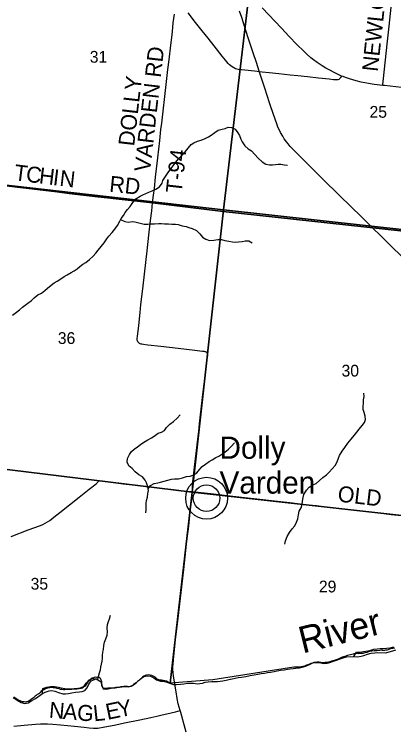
# Model space of a CAD drawing. Extents: x 1410790 to 1770854, y 566777 to 831614.
# Drawn here: x 1630046 to 1637179, y 668904 to 682381 of the extents above; entities that cross this region are included whole.
import ezdxf

# ---------------------------------------------------------------- set-up
doc = ezdxf.new("R2010")
doc.units = 0
for name, color, linetype in [('GM_X_County_Road', 7, 'Continuous'), ('GM_X_County_Road_Text', 7, 'Continuous'), ('GM_X_Major_River', 7, 'Continuous'), ('GM_X_Major_River_Text', 7, 'Continuous'), ('GM_X_Minor_River', 7, 'Continuous'), ('GM_X_Rail_Line', 7, 'Continuous'), ('GM_X_Section', 7, 'Continuous'), ('GM_X_Section_Text', 7, 'Continuous'), ('GM_X_State_Route', 7, 'Continuous'), ('GM_X_Township', 7, 'Continuous'), ('GM_X_Township_Road', 7, 'Continuous'), ('GM_X_Township_Road_Text', 7, 'Continuous'), ('GM_X_Unincorporated', 7, 'Continuous'), ('GM_X_Unincorporated_Location', 7, 'Continuous'), ('GM_X_Unincorporated_Text', 7, 'Continuous')]:
    doc.layers.add(name, color=color, linetype=linetype)

msp = doc.modelspace()

# ---------------------------------------------------------------- linework, layer by layer
at = {"layer": 'GM_X_County_Road'}
for points in [[(1636200, 681222), (1636180, 681193), (1636170, 681181), (1636159, 681170), (1636145, 681159), (1636129, 681152), (1636112, 681149), (1636095, 681148), (1636046, 681151), (1635964, 681160), (1635768, 681184), (1635556, 681207), (1635377, 681226), (1635230, 681240), (1635018, 681262), (1634838, 681281), (1634708, 681296), (1634561, 681311), (1634382, 681329), (1634317, 681336), (1634284, 681341), (1634254, 681346), (1634229, 681353), (1634208, 681360), (1634188, 681369), (1634173, 681376), (1634144, 681393), (1634117, 681413), (1634092, 681434), (1634068, 681458), (1634014, 681520), (1633953, 681597), (1633802, 681791), (1633689, 681932), (1633577, 682073), (1633455, 682228), (1633313, 682408)], [(1628105, 674058), (1628109, 674057), (1628154, 674047), (1628219, 674034), (1628284, 674024), (1628365, 674014), (1628512, 673998), (1628789, 673966), (1629017, 673938), (1629164, 673921), (1629408, 673892), (1629685, 673861), (1629782, 673849), (1630157, 673802), (1630320, 673782), (1630483, 673762), (1631020, 673696), (1631167, 673679), (1631509, 673637), (1631640, 673621)], [(1631640, 673621), (1631720, 673611), (1631916, 673586), (1632095, 673563), (1632323, 673536), (1632681, 673494), (1632991, 673457), (1633333, 673419), (1633393, 673413)], [(1633393, 673413), (1633790, 673372), (1634051, 673342), (1634377, 673303), (1634605, 673278), (1634996, 673233), (1635224, 673207), (1635420, 673186), (1635583, 673168), (1635730, 673150), (1635860, 673135), (1636072, 673111), (1636398, 673073), (1636675, 673040), (1636854, 673019), (1637131, 672987), (1637392, 672959)]]:
    msp.add_lwpolyline(points, dxfattribs=at)
at = {"layer": 'GM_X_Major_River'}
for points in [[(1636430, 670314), (1636482, 670397), (1636542, 670398), (1636614, 670407), (1636691, 670421), (1636748, 670436), (1636806, 670451), (1636875, 670463), (1636925, 670466), (1636975, 670467), (1637044, 670472), (1637116, 670481), (1637183, 670495)], [(1636430, 670314), (1636498, 670307), (1636569, 670323), (1636621, 670334), (1636690, 670359), (1636755, 670378), (1636827, 670388), (1636877, 670389), (1637030, 670386), (1637095, 670403), (1637165, 670423), (1637220, 670444)], [(1631583, 669895), (1631681, 669841), (1631683, 669774), (1631714, 669708), (1631786, 669704), (1631837, 669715), (1631897, 669730), (1631952, 669737), (1632026, 669743), (1632117, 669750), (1632191, 669744), (1632266, 669771), (1632344, 669829), (1632411, 669890), (1632482, 669941), (1632553, 669953), (1632607, 669944), (1632667, 669913), (1632718, 669876), (1632792, 669854), (1632852, 669853), (1632912, 669836), (1632982, 669806), (1633040, 669791), (1633098, 669788), (1633171, 669794), (1633231, 669803), (1633303, 669812), (1633362, 669817), (1633416, 669813), (1633482, 669800), (1633534, 669807), (1633585, 669818), (1633635, 669831), (1633694, 669842), (1633758, 669849), (1633815, 669848), (1633865, 669849), (1633915, 669854), (1633969, 669860), (1634028, 669871), (1634080, 669882), (1634143, 669897), (1634199, 669908), (1634254, 669919), (1634320, 669930), (1634399, 669942), (1634478, 669956), (1634556, 669969), (1634625, 669982), (1634685, 669994), (1634752, 670005), (1634806, 670014), (1634865, 670023), (1634931, 670035), (1634988, 670046), (1635050, 670057), (1635121, 670066), (1635185, 670076), (1635236, 670083), (1635288, 670092), (1635340, 670099), (1635411, 670106), (1635486, 670123), (1635540, 670139), (1635609, 670174), (1635672, 670201), (1635740, 670206), (1635807, 670198), (1635859, 670187), (1635927, 670190), (1635979, 670201), (1636030, 670224), (1636101, 670248), (1636174, 670275), (1636228, 670290), (1636295, 670307), (1636430, 670314)], [(1630573, 669620), (1630583, 669714), (1630656, 669739), (1630725, 669754), (1630801, 669750), (1630875, 669737), (1630927, 669725), (1630999, 669712), (1631065, 669709), (1631116, 669710), (1631172, 669712), (1631242, 669719), (1631293, 669726), (1631360, 669759), (1631399, 669818), (1631455, 669879), (1631521, 669902), (1631583, 669895)], [(1630573, 669620), (1630626, 669643), (1630699, 669670), (1630749, 669675), (1630807, 669666), (1630875, 669638), (1630957, 669617), (1631011, 669615), (1631068, 669624), (1631128, 669633), (1631197, 669644), (1631269, 669650), (1631319, 669659), (1631370, 669676), (1631417, 669730), (1631447, 669795), (1631494, 669856), (1631583, 669895)], [(1630025, 669547), (1630101, 669496), (1630174, 669452), (1630242, 669435), (1630307, 669445), (1630378, 669488), (1630443, 669529), (1630573, 669620)]]:
    msp.add_lwpolyline(points, dxfattribs=at)
at = {"layer": 'GM_X_Minor_River'}
for points in [[(1632636, 679065), (1632709, 679098), (1632779, 679137), (1632824, 679207), (1632841, 679259), (1632888, 679331), (1632942, 679408), (1632989, 679478), (1633036, 679535), (1633081, 679605), (1633133, 679669), (1633202, 679734), (1633259, 679795), (1633314, 679869), (1633369, 679935), (1633419, 679966), (1633493, 679997), (1633560, 680017), (1633634, 680048), (1633697, 680079), (1633749, 680113), (1633814, 680158), (1633882, 680202), (1633953, 680223), (1634011, 680238), (1634069, 680258), (1634132, 680255), (1634197, 680221), (1634251, 680154), (1634282, 680103), (1634308, 680037), (1634331, 679985), (1634383, 679912), (1634442, 679854), (1634506, 679815), (1634566, 679748), (1634631, 679681), (1634707, 679612), (1634778, 679566), (1634846, 679553), (1634901, 679552), (1634955, 679558), (1635009, 679567), (1635059, 679567), (1635123, 679556), (1635185, 679549)], [(1630009, 676728), (1630088, 676783), (1630142, 676831), (1630197, 676880), (1630252, 676916), (1630302, 676957), (1630367, 677007), (1630419, 677056), (1630488, 677108), (1630557, 677145), (1630619, 677192), (1630670, 677234), (1630736, 677291), (1630793, 677335), (1630851, 677370), (1630920, 677412), (1630983, 677453), (1631041, 677485), (1631114, 677530), (1631172, 677563), (1631227, 677601), (1631277, 677642), (1631334, 677684), (1631390, 677721), (1631461, 677775), (1631530, 677838), (1631578, 677896), (1631621, 677949), (1631680, 678021), (1631735, 678086), (1631785, 678160), (1631824, 678216), (1631883, 678285), (1631934, 678347), (1631984, 678416), (1632029, 678492), (1632054, 678544), (1632098, 678604), (1632131, 678655), (1632176, 678711), (1632224, 678770), (1632273, 678844), (1632332, 678912), (1632413, 678965), (1632465, 678990), (1632522, 679012), (1632574, 679037), (1632636, 679065)], [(1632045, 678525), (1632123, 678491), (1632194, 678478), (1632264, 678486), (1632314, 678483), (1632388, 678462), (1632440, 678448), (1632490, 678439), (1632558, 678437), (1632614, 678444), (1632684, 678443), (1632761, 678451), (1632815, 678454), (1632871, 678447), (1632943, 678443), (1633007, 678440), (1633077, 678437), (1633129, 678431), (1633203, 678410), (1633275, 678395), (1633329, 678377), (1633391, 678356), (1633469, 678321), (1633533, 678257), (1633584, 678196), (1633650, 678155), (1633716, 678134), (1633798, 678136), (1633870, 678149), (1633941, 678152), (1634005, 678134), (1634077, 678117), (1634149, 678106), (1634205, 678103), (1634259, 678107), (1634331, 678116), (1634387, 678126), (1634453, 678123), (1634519, 678090)], [(1635133, 672426), (1635148, 672492), (1635179, 672569), (1635218, 672643), (1635273, 672717), (1635323, 672768), (1635354, 672838), (1635375, 672904), (1635387, 672978), (1635400, 673048), (1635437, 673112), (1635458, 673181), (1635466, 673235), (1635475, 673304), (1635489, 673357), (1635538, 673439), (1635591, 673495), (1635662, 673542), (1635720, 673569), (1635787, 673621), (1635847, 673678), (1635914, 673732), (1635969, 673777), (1636025, 673839), (1636082, 673904), (1636115, 673974), (1636144, 674042), (1636162, 674094), (1636211, 674173), (1636260, 674243), (1636315, 674325), (1636380, 674398), (1636435, 674470), (1636489, 674533), (1636532, 674587), (1636589, 674656), (1636633, 674714), (1636650, 674766), (1636645, 674830), (1636627, 674900), (1636608, 674958), (1636608, 675009), (1636611, 675079), (1636609, 675137), (1636622, 675201), (1636617, 675265)], [(1632519, 673013), (1632527, 673073), (1632528, 673139), (1632525, 673195), (1632533, 673249), (1632548, 673307), (1632559, 673381), (1632571, 673435), (1632556, 673501), (1632532, 673576), (1632509, 673630), (1632457, 673691), (1632388, 673731), (1632320, 673784), (1632260, 673847), (1632201, 673900), (1632169, 673970), (1632176, 674038), (1632211, 674114), (1632249, 674165), (1632300, 674213), (1632365, 674256), (1632417, 674296), (1632484, 674341), (1632556, 674387), (1632623, 674424), (1632673, 674454), (1632750, 674509), (1632816, 674530), (1632869, 674564), (1632909, 674617), (1632970, 674683), (1633041, 674734), (1633106, 674794), (1633166, 674857)], [(1632564, 673465), (1632608, 673527), (1632673, 673568), (1632743, 673580), (1632793, 673593), (1632864, 673612), (1632932, 673628), (1633004, 673649), (1633058, 673653), (1633135, 673654), (1633207, 673673), (1633283, 673696), (1633354, 673706), (1633404, 673723), (1633476, 673766), (1633535, 673834), (1633576, 673888), (1633638, 673931), (1633711, 673980), (1633766, 674014), (1633834, 674057), (1633889, 674079), (1633951, 674118), (1634004, 674152), (1634074, 674209), (1634123, 674261), (1634184, 674332)], [(1631612, 669879), (1631631, 669939), (1631645, 670007), (1631664, 670065), (1631674, 670117), (1631687, 670171), (1631700, 670229), (1631706, 670281), (1631703, 670337), (1631709, 670397), (1631720, 670449), (1631730, 670521), (1631743, 670583), (1631764, 670651), (1631789, 670717), (1631797, 670777), (1631794, 670849), (1631801, 670919), (1631819, 670971), (1631836, 671023), (1631854, 671093)]]:
    msp.add_lwpolyline(points, dxfattribs=at)
at = {"layer": 'GM_X_Rail_Line'}
msp.add_lwpolyline([(1637329, 677836), (1637141, 678021), (1636581, 678568), (1636163, 678979), (1635850, 679285), (1635368, 679758), (1635318, 679811), (1635235, 679897), (1635194, 679948), (1635166, 679984), (1635123, 680044), (1635092, 680093), (1635052, 680163), (1635024, 680220), (1635004, 680264), (1634988, 680304), (1634948, 680409), (1634869, 680645), (1634846, 680717), (1634800, 680857), (1634754, 680995), (1634707, 681142), (1634650, 681314), (1634598, 681475), (1634537, 681659), (1634445, 681942), (1634367, 682178), (1634321, 682319), (1634280, 682441)], dxfattribs=at)
at = {"layer": 'GM_X_Section'}
for points in [[(1629292, 684562), (1634606, 684004), (1633977, 678706), (1628678, 679311)], [(1634606, 684004), (1639895, 683441), (1639320, 678118), (1633977, 678706)], [(1628678, 679311), (1633977, 678706), (1633389, 673402), (1628111, 674047), (1628145, 674379)], [(1633977, 678706), (1639320, 678118), (1638802, 672801), (1633389, 673402)]]:
    msp.add_lwpolyline(points, close=True, dxfattribs=at)
for points in [[(1628111, 674047), (1633389, 673402), (1632979, 669812), (1632965, 669812), (1632937, 669831), (1632907, 669851), (1632879, 669862), (1632843, 669868), (1632815, 669874), (1632791, 669873), (1632765, 669877), (1632750, 669883), (1632732, 669893), (1632704, 669918), (1632670, 669940), (1632631, 669959), (1632599, 669965), (1632567, 669970), (1632533, 669968), (1632507, 669958), (1632484, 669947), (1632456, 669927), (1632426, 669898), (1632403, 669872), (1632365, 669844), (1632335, 669821), (1632290, 669793), (1632260, 669768), (1632244, 669754), (1632226, 669752), (1632200, 669748), (1632176, 669751), (1632146, 669755), (1632104, 669750), (1632050, 669744), (1632006, 669733), (1631976, 669725), (1631942, 669724), (1631890, 669723), (1631838, 669721), (1631806, 669720), (1631772, 669716), (1631744, 669716), (1631730, 669717), (1631714, 669727), (1631702, 669753), (1631696, 669779), (1631693, 669817), (1631689, 669845), (1631680, 669873), (1631666, 669901), (1631656, 669914), (1631644, 669922), (1631618, 669928), (1631592, 669924), (1631574, 669925), (1631550, 669921), (1631532, 669915), (1631512, 669907), (1631494, 669900), (1631478, 669886), (1631458, 669868), (1631429, 669843), (1631415, 669821), (1631399, 669793), (1631376, 669761), (1631356, 669744), (1631326, 669724), (1631300, 669716), (1631266, 669707), (1631224, 669705), (1631179, 669700), (1631125, 669695), (1631079, 669693), (1630999, 669690), (1630969, 669691), (1630941, 669693), (1630914, 669699), (1630890, 669708), (1630852, 669714), (1630814, 669725), (1630778, 669729), (1630746, 669734), (1630712, 669728), (1630670, 669719), (1630632, 669707), (1630601, 669691), (1630571, 669676), (1630549, 669662), (1630533, 669642), (1630523, 669626), (1630506, 669613), (1630492, 669611), (1630474, 669599), (1630454, 669583), (1630438, 669568), (1630406, 669540), (1630367, 669515), (1630335, 669491), (1630309, 669473), (1630275, 669464), (1630257, 669460), (1630231, 669462), (1630199, 669467), (1630155, 669483), (1630129, 669490), (1630093, 669512), (1630059, 669531), (1630034, 669551)], [(1637202, 670475), (1637164, 670467), (1637122, 670458), (1637090, 670450), (1637056, 670437), (1637026, 670433), (1637008, 670427), (1636990, 670426), (1636968, 670428), (1636950, 670432), (1636918, 670429), (1636860, 670425), (1636810, 670424), (1636768, 670417), (1636720, 670407), (1636675, 670394), (1636637, 670382), (1636599, 670373), (1636557, 670371), (1636515, 670368), (1636477, 670372), (1636457, 670369), (1636433, 670365), (1636417, 670361), (1636391, 670353), (1636365, 670348), (1636337, 670342), (1636313, 670336), (1636260, 670315), (1636208, 670302), (1636172, 670286), (1636136, 670269), (1636098, 670255), (1636063, 670242), (1636009, 670226), (1635977, 670213), (1635931, 670206), (1635893, 670202), (1635865, 670198), (1635837, 670199), (1635811, 670205), (1635779, 670207), (1635753, 670212), (1635737, 670208), (1635713, 670206), (1635679, 670201), (1635651, 670191), (1635619, 670182), (1635585, 670168), (1635542, 670153), (1635504, 670137), (1635470, 670128), (1635438, 670122), (1635408, 670118), (1635374, 670115), (1635352, 670117), (1635330, 670117), (1635314, 670118), (1635300, 670116), (1633779, 669878), (1632979, 669812), (1633389, 673402), (1638802, 672801)]]:
    msp.add_lwpolyline(points, dxfattribs=at)
at = {"layer": 'GM_X_State_Route'}
msp.add_lwpolyline([(1637538, 680984), (1637009, 681042), (1636975, 681046), (1636813, 681064), (1636707, 681080), (1636637, 681091), (1636571, 681105), (1636476, 681130), (1636351, 681167), (1636273, 681194), (1636231, 681210), (1636200, 681222), (1636137, 681250), (1636063, 681285), (1635976, 681330), (1635905, 681371), (1635835, 681414), (1635740, 681477), (1635673, 681525), (1635622, 681566), (1635548, 681630), (1635488, 681686), (1635361, 681814), (1635212, 681966), (1635067, 682122), (1634707, 682505)], dxfattribs=at)
at = {"layer": 'GM_X_Township'}
for points in [[(1629570, 687086), (1628688, 679300), (1629255, 679234), (1630852, 679046), (1631080, 679016), (1631617, 678954), (1631797, 678934), (1631960, 678917), (1632647, 678842), (1633970, 678678), (1639318, 678094), (1644674, 677520), (1649879, 677009), (1656836, 676404), (1657686, 676331), (1659011, 676224), (1669822, 675181), (1671693, 682151), (1671974, 683181)], [(1639318, 678094), (1633970, 678678), (1632647, 678842), (1631960, 678917), (1631797, 678934), (1631617, 678954), (1631080, 679016), (1630852, 679046), (1629255, 679234), (1628688, 679300), (1628103, 674059), (1627873, 671881), (1627499, 668268), (1626861, 663024), (1626163, 656988), (1625996, 655541), (1625665, 652643), (1625522, 651392), (1625424, 650665), (1626598, 650535), (1631173, 650097), (1636122, 649546), (1640009, 649114)]]:
    msp.add_lwpolyline(points, dxfattribs=at)
at = {"layer": 'GM_X_Township_Road'}
for points in [[(1636975, 681046), (1636976, 681065), (1636986, 681174), (1637055, 681819), (1637093, 682161), (1637144, 682634)], [(1632647, 678842), (1632664, 678981), (1632679, 679111), (1632703, 679323), (1632743, 679682), (1632780, 680008), (1632804, 680219), (1632817, 680334), (1632844, 680562), (1632876, 680839), (1632908, 681116), (1632934, 681344), (1632956, 681523), (1632987, 681800), (1633005, 681947), (1633018, 682061), (1633035, 682224), (1633055, 682387)], [(1628688, 679300), (1629255, 679234), (1629533, 679205), (1629859, 679169), (1630153, 679137), (1630299, 679117), (1630527, 679089), (1630608, 679079), (1630852, 679046), (1631080, 679016), (1631617, 678954), (1631797, 678934), (1631960, 678917), (1632270, 678885), (1632531, 678856), (1632647, 678842)], [(1633393, 673413), (1633394, 673452), (1633396, 673501), (1633405, 673599), (1633437, 673876), (1633472, 674185), (1633497, 674397), (1633513, 674544), (1633530, 674691), (1633549, 674854), (1633587, 675179), (1633665, 675848), (1633682, 675978), (1633682, 675988), (1633682, 675996), (1633681, 676002), (1633680, 676007), (1633677, 676013), (1633675, 676017), (1633672, 676022), (1633669, 676025), (1633665, 676028), (1633660, 676032), (1633652, 676036), (1633643, 676039), (1633635, 676041), (1633619, 676045), (1633602, 676047), (1633586, 676048), (1633439, 676065), (1633129, 676101), (1632803, 676139), (1632559, 676166), (1632477, 676176), (1632445, 676181), (1632430, 676186), (1632415, 676191), (1632401, 676198), (1632388, 676208), (1632378, 676218), (1632369, 676231), (1632363, 676245), (1632359, 676260), (1632358, 676276), (1632357, 676292), (1632360, 676325), (1632388, 676536), (1632414, 676781), (1632428, 676928), (1632461, 677221), (1632491, 677498), (1632542, 677939), (1632575, 678232), (1632608, 678509), (1632629, 678688), (1632647, 678842)], [(1629986, 672573), (1630308, 672694), (1630538, 672779), (1630584, 672798), (1630628, 672819), (1630670, 672844), (1630711, 672872), (1630789, 672932), (1630904, 673024), (1631263, 673309), (1631456, 673461), (1631585, 673563), (1631597, 673573), (1631604, 673579), (1631609, 673585), (1631614, 673591), (1631623, 673601), (1631637, 673617), (1631640, 673621)], [(1633163, 669302), (1633145, 669365), (1633129, 669429), (1633110, 669525), (1633088, 669655), (1633042, 669946), (1633034, 670011), (1633029, 670076), (1633028, 670101), (1633028, 670125), (1633030, 670174), (1633044, 670321), (1633079, 670631), (1633126, 671038), (1633194, 671625), (1633231, 671951), (1633272, 672310), (1633293, 672489), (1633313, 672668), (1633325, 672766), (1633348, 672962), (1633366, 673125), (1633382, 673271), (1633393, 673403), (1633393, 673413)], [(1630034, 669010), (1630230, 669026), (1630442, 669045), (1630540, 669051), (1630606, 669053), (1630672, 669051), (1630770, 669044), (1630917, 669031), (1631178, 669006), (1631357, 668987), (1631455, 668977), (1631537, 668971), (1631585, 668969), (1631618, 668971), (1631650, 668975), (1631714, 668988), (1631955, 669035), (1632116, 669067), (1632405, 669125), (1632613, 669170), (1632725, 669195), (1632804, 669215), (1632995, 669260), (1633074, 669279), (1633163, 669302)], [(1633277, 668892), (1633239, 669034), (1633197, 669192), (1633176, 669262), (1633163, 669302)]]:
    msp.add_lwpolyline(points, dxfattribs=at)
at = {"layer": 'GM_X_Unincorporated'}
for radius in [393, 249]:
    msp.add_circle((1633661, 673290), radius, dxfattribs=at)
at = {"layer": 'GM_X_Unincorporated_Location'}
msp.add_line((1633661, 673290), (1633661, 673290), dxfattribs=at)

# ---------------------------------------------------------------- texts
at = {"layer": 'GM_X_County_Road_Text'}
msp.add_text('OLD', height=300, rotation=353.3648, dxfattribs=at).set_placement((1636115, 673229))
at = {"layer": 'GM_X_Major_River_Text'}
msp.add_text('River', height=500, rotation=13.994, dxfattribs=at).set_placement((1635466, 670371))
at = {"layer": 'GM_X_Section_Text'}
for s, p in [('31', (1631465, 681472)), ('25', (1636725, 680438)), ('36', (1630864, 676188)), ('30', (1636199, 675576)), ('35', (1630352, 671572)), ('29', (1635773, 671520))]:
    msp.add_text(s, height=221, rotation=0, dxfattribs=at).set_placement(p)
at = {"layer": 'GM_X_Township_Road_Text'}
for s, rotation, p in [('NEWLOVE', 83.9036, (1636881, 681295)), ('VARDEN RD', 83.5168, (1632598, 679411)), ('DOLLY', 83.5038, (1632299, 679894)), ('T-94', 83.6076, (1633192, 679011)), ('T', 352.943, (1630031, 679266)), ('C', 352.9432, (1630254, 679238)), ('H', 352.9405, (1630499, 679208)), ('I', 352.9659, (1630761, 679175)), ('N', 353.4451, (1630886, 679160)), ('RD', 354.1372, (1631823, 679050)), ('Y', 11.3167, (1632017, 669170)), ('N', 354.7287, (1630690, 669168)), ('A', 354.729, (1630953, 669144)), ('G', 354.8107, (1631216, 669120)), ('L', 6.1324, (1631544, 669097)), ('E', 11.5639, (1631797, 669125))]:
    msp.add_text(s, height=300, rotation=rotation, dxfattribs=at).set_placement(p)
at = {"layer": 'GM_X_Unincorporated_Text'}
for s, p in [('Dolly', (1633905, 674031)), ('Varden', (1633905, 673376))]:
    msp.add_text(s, height=417, rotation=0, dxfattribs=at).set_placement(p)

doc.saveas('drawing.dxf')
